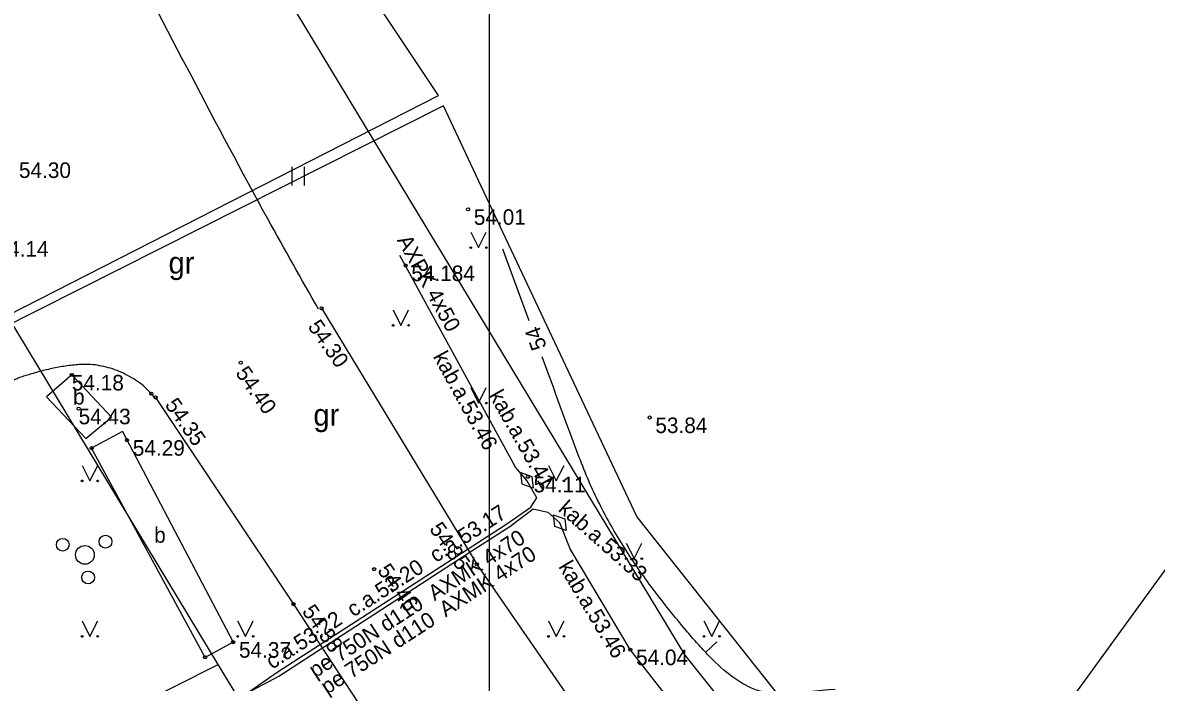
# Model space of a CAD drawing. Extents: x 578395 to 578590, y 418519 to 418816.
# Drawn here: x 578485.34 to 578521.8, y 418556.02 to 418577.23 of the extents above; entities that cross this region are included whole.
import ezdxf

# ---------------------------------------------------------------- set-up
doc = ezdxf.new("R2010")
doc.units = 0
for name, color, linetype in [('BUVE_BDET_####_####_#', 7, 'Continuous'), ('BUVE_BDET_####_TKST_#', 7, 'Continuous'), ('CELI_CMAL_####_####_#', 7, 'Continuous'), ('CELI_CSEG_####_TKST_#', 7, 'Continuous'), ('ELEK_ACRL_####_####_#', 7, 'Continuous'), ('ELEK_ACRL_####_TKST_#', 7, 'Continuous'), ('ELEK_ELEM_####_####_#', 7, 'Continuous'), ('ELEK_VADP_ZSPR_####_#', 7, 'Continuous'), ('ELEK_VADP_ZSPR_####_I', 7, 'Continuous'), ('ELEK_VADP_ZSPR_TKST_#', 7, 'Continuous'), ('ELEK_VADP_ZSPR_TKST_I', 7, 'Continuous'), ('RAMI_PLAN_####_TKST_#', 7, 'Continuous'), ('RELJ_AATZ_####_TKST_#', 7, 'Continuous'), ('RELJ_ELEM_####_####_#', 7, 'Continuous'), ('RELJ_HORZ_####_TKST_#', 7, 'Continuous'), ('RELJ_HORZ_RESN_####_#', 7, 'Continuous'), ('ROBZ_UZMR_####_####_#', 7, 'Continuous'), ('TERT_ELEM_####_####_#', 7, 'Continuous')]:
    doc.layers.add(name, color=color, linetype=linetype)

msp = doc.modelspace()

# ---------------------------------------------------------------- linework, layer by layer
at = {"layer": 'BUVE_BDET_####_####_#'}
for p, q in [((578488.545, 418564.091), (578487.553, 418563.554)), ((578488.545, 418564.091), (578492.108, 418557.315)), ((578491.201, 418556.824), (578487.553, 418563.554)), ((578492.108, 418557.315), (578491.201, 418556.824))]:
    msp.add_line(p, q, dxfattribs=at)
msp.add_lwpolyline([(578486.917, 418565.908), (578486.097, 418565.2), (578487.369, 418563.868), (578488.193, 418564.552), (578486.917, 418565.908)], dxfattribs=at)
at = {"layer": 'CELI_CMAL_####_####_#'}
for points in [[(578494.951, 418568.05), (578499.945, 418559.817), (578500, 418559.737)], [(578489.611, 418565.18), (578494.048, 418558.537), (578500, 418549.461)], [(578500, 418559.737), (578506.766, 418549.939)]]:
    msp.add_lwpolyline(points, dxfattribs=at)
for points in [[(578494.854, 418568.017), (578493.222, 418570.924), (578490.763, 418575.52), (578488.331, 418580.13), (578485.806, 418584.688), (578479.899, 418594.609), (578471.211, 418607.779)], [(578489.589, 418565.162), (578489.474, 418565.302), (578489.267, 418565.515), (578489.033, 418565.697), (578488.777, 418565.854), (578488.508, 418565.991), (578488.231, 418566.099), (578487.946, 418566.175), (578487.378, 418566.248), (578487.157, 418566.239), (578486.936, 418566.22), (578486.495, 418566.155), (578486.273, 418566.111), (578486.052, 418566.06), (578485.834, 418566.002), (578485.615, 418565.94), (578485.445, 418565.89), (578485.276, 418565.835), (578485.114, 418565.767), (578484.962, 418565.679), (578480.688, 418562.724)]]:
    msp.add_spline(points, degree=3, dxfattribs=at)
at = {"layer": 'ELEK_ACRL_####_####_#'}
for points in [[(578500, 418560.526), (578500.878, 418561.093)], [(578500, 418560.387), (578501.002, 418561.037)], [(578493.524, 418556.347), (578500, 418560.526)], [(578493.577, 418556.224), (578500, 418560.387)]]:
    msp.add_lwpolyline(points, dxfattribs=at)
at = {"layer": 'ELEK_ELEM_####_####_#'}
for points in [[(578501.356, 418562.767), (578501.712, 418562.642), (578501.756, 418562.267), (578501.4, 418562.392)], [(578502.814, 418560.906), (578502.458, 418561.031), (578502.414, 418561.406), (578502.77, 418561.281)]]:
    msp.add_lwpolyline(points, close=True, dxfattribs=at)
at = {"layer": 'ELEK_VADP_ZSPR_####_#'}
for points in [[(578479.187, 418564.935), (578498.707, 418574.895), (578493.264, 418583.075), (578485.065, 418590.965)], [(578500, 418572.157), (578498.867, 418574.559), (578479.335, 418564.716)], [(578521.251, 418540.371), (578510.48, 418554.563), (578505.094, 418561.359), (578500, 418572.157)], [(578500, 418565.116), (578497.464, 418569.749)], [(578501.556, 418562.517), (578501.191, 418562.94), (578500, 418565.116)], [(578508.955, 418551.863), (578504.881, 418557.075), (578502.948, 418560.316), (578502.614, 418561.156)]]:
    msp.add_lwpolyline(points, dxfattribs=at)
at = {"layer": 'ELEK_VADP_ZSPR_####_I'}
for points in [[(578500, 418560.526), (578500.878, 418561.093), (578501.678, 418561.653), (578501.876, 418561.951), (578501.556, 418562.517)], [(578500, 418560.387), (578501.002, 418561.037), (578501.752, 418561.597), (578502.228, 418561.499), (578502.614, 418561.156)], [(578492.567, 418555.687), (578493.524, 418556.347), (578500, 418560.526)], [(578492.567, 418555.687), (578493.577, 418556.224), (578500, 418560.387)]]:
    msp.add_lwpolyline(points, dxfattribs=at)
at = {"layer": 'RAMI_PLAN_####_TKST_#'}
msp.add_line((578500.351, 418519.111), (578500.351, 418667.611), dxfattribs=at)
at = {"layer": 'RELJ_ELEM_####_####_#'}
for centre in [(578499.661, 418571.234), (578497.652, 418569.425), (578494.951, 418568.05), (578492.349, 418566.301), (578486.917, 418565.908), (578489.474, 418565.302), (578489.611, 418565.18), (578487.136, 418564.82), (578505.501, 418564.538), (578488.693, 418563.81), (578487.553, 418563.554), (578501.585, 418562.632), (578499.945, 418559.817), (578496.641, 418559.662), (578494.048, 418558.537), (578492.108, 418557.315), (578491.201, 418556.824), (578504.881, 418557.075)]:
    msp.add_circle(centre, 0.05, dxfattribs=at)
at = {"layer": 'RELJ_HORZ_RESN_####_#'}
for p, q in [((578501.625, 418567.648), (578500.777, 418569.955)), ((578507.667, 418557.325), (578507.303, 418556.982))]:
    msp.add_line(p, q, dxfattribs=at)
msp.add_spline([(578511.475, 418555.796), (578509.769, 418555.66), (578509.541, 418555.655), (578509.319, 418555.678), (578508.888, 418555.794), (578508.084, 418556.26), (578507.35, 418556.933), (578507.008, 418557.307), (578506.682, 418557.685), (578506.133, 418558.351), (578505.615, 418559.017), (578504.68, 418560.369), (578503.885, 418561.771), (578503.544, 418562.502), (578503.241, 418563.256), (578502.051, 418566.491)], degree=3, dxfattribs=at)
at = {"layer": 'ROBZ_UZMR_####_####_#'}
for p, q in [((578469.515, 418618.285), (578506.631, 418556.899)), ((578491.621, 418556.597), (578468.202, 418595.33)), ((578513.707, 418548.097), (578533.748, 418575.711)), ((578506.631, 418556.899), (578513.707, 418548.097)), ((578440.85, 418531.07), (578491.621, 418556.597)), ((578496.218, 418549.102), (578491.621, 418556.597))]:
    msp.add_line(p, q, dxfattribs=at)
at = {"layer": 'TERT_ELEM_####_####_#'}
for p, q in [((578494, 418572), (578494, 418572.6)), ((578494.4, 418572), (578494.4, 418572.6)), ((578499.75, 418570.5), (578500, 418570)), ((578500, 418570), (578500.25, 418570.5)), ((578497.25, 418568), (578497.5, 418567.5)), ((578497.5, 418567.5), (578497.75, 418568)), ((578499.75, 418565.5), (578500, 418565)), ((578500, 418565), (578500.25, 418565.5)), ((578487.25, 418563), (578487.5, 418562.5)), ((578487.5, 418562.5), (578487.75, 418563)), ((578502.25, 418563), (578502.5, 418562.5)), ((578502.5, 418562.5), (578502.75, 418563)), ((578504.75, 418560.5), (578505, 418560)), ((578505, 418560), (578505.25, 418560.5)), ((578487.25, 418558), (578487.5, 418557.5)), ((578487.5, 418557.5), (578487.75, 418558)), ((578492.25, 418558), (578492.5, 418557.5)), ((578492.5, 418557.5), (578492.75, 418558)), ((578502.25, 418558), (578502.5, 418557.5)), ((578502.5, 418557.5), (578502.75, 418558)), ((578507.25, 418558), (578507.5, 418557.5)), ((578507.5, 418557.5), (578507.75, 418558))]:
    msp.add_line(p, q, dxfattribs=at)
for centre, radius in [((578499.75, 418570), 0.028), ((578500.25, 418570), 0.0263), ((578497.25, 418567.5), 0.028), ((578497.75, 418567.5), 0.0263), ((578499.75, 418565), 0.028), ((578500.25, 418565), 0.0263), ((578487.25, 418562.5), 0.028), ((578487.75, 418562.5), 0.0263), ((578502.25, 418562.5), 0.028), ((578502.75, 418562.5), 0.0263), ((578486.625, 418560.446), 0.204), ((578488, 418560.547), 0.207), ((578487.339, 418560.122), 0.301), ((578504.75, 418560), 0.028), ((578505.25, 418560), 0.0263), ((578487.442, 418559.394), 0.205), ((578487.25, 418557.5), 0.028), ((578487.75, 418557.5), 0.0263), ((578492.25, 418557.5), 0.028), ((578492.75, 418557.5), 0.0263), ((578502.25, 418557.5), 0.028), ((578502.75, 418557.5), 0.0263), ((578507.25, 418557.5), 0.028), ((578507.75, 418557.5), 0.0263)]:
    msp.add_circle(centre, radius, dxfattribs=at)

# ---------------------------------------------------------------- texts
at = {"layer": 'BUVE_BDET_####_TKST_#'}
for p in [(578486.957, 418564.955), (578489.565, 418560.511)]:
    msp.add_text('b', height=0.5, dxfattribs=at).set_placement(p)
at = {"layer": 'CELI_CSEG_####_TKST_#'}
for p in [(578490.028, 418569.164), (578494.688, 418564.273)]:
    msp.add_text('gr', height=0.7, dxfattribs=at).set_placement(p)
at = {"layer": 'ELEK_ACRL_####_TKST_#'}
for s, rotation, p in [('c.a.53.17', 32.8367, (578498.631, 418559.855)), ('c.a.53.20', 32.8367, (578495.973, 418558.106)), ('pe 750N d110', 32.9519, (578494.749, 418556.148)), ('c.a.53.22', 33.2577, (578493.363, 418556.425)), ('pe 750N d110', 32.9519, (578495.128, 418555.619))]:
    msp.add_text(s, height=0.5, rotation=rotation, dxfattribs=at).set_placement(p)
at = {"layer": 'ELEK_VADP_ZSPR_TKST_#'}
for s, rotation, p in [('AXPK 4x50', 298.6923, (578497.366, 418570.241)), ('kab.a.53.46', 298.6923, (578498.524, 418566.5)), ('kab.a.53.46', 300.8127, (578502.557, 418559.745))]:
    msp.add_text(s, height=0.5, rotation=rotation, dxfattribs=at).set_placement(p)
at = {"layer": 'ELEK_VADP_ZSPR_TKST_I'}
for s, rotation, p in [('kab.a.53.41', 299.4826, (578500.319, 418565.252)), ('kab.a.53.33', 318.3519, (578502.534, 418561.552)), ('AXMK 4x70', 32.9519, (578498.586, 418558.625)), ('AXMK 4x70', 32.8367, (578498.94, 418558.106))]:
    msp.add_text(s, height=0.5, rotation=rotation, dxfattribs=at).set_placement(p)
at = {"layer": 'RELJ_AATZ_####_TKST_#'}
for s, p in [('54.30', (578485.216, 418572.241)), (' 54.01', (578499.661, 418570.734)), ('54.14', (578484.495, 418569.712)), (' 54.184', (578497.652, 418568.925)), ('54.18', (578486.917, 418565.408)), ('54.43', (578487.136, 418564.32)), (' 53.84', (578505.501, 418564.038)), (' 54.29', (578488.693, 418563.31)), (' 54.11', (578501.585, 418562.132)), (' 54.37', (578492.108, 418556.815)), (' 54.04', (578504.881, 418556.575))]:
    msp.add_text(s, height=0.5, dxfattribs=at).set_placement(p)
for s, p in [(' 54.30', (578494.381, 418567.611)), (' 54.40', (578492.057, 418566.117)), (' 54.35', (578489.786, 418565.095)), (' 54.35', (578498.293, 418561.105)), (' 54.46', (578496.621, 418559.769)), (' 54.38', (578494.196, 418558.454))]:
    msp.add_text(s, height=0.5, rotation=305, dxfattribs=at).set_placement(p)
at = {"layer": 'RELJ_HORZ_####_TKST_#'}
msp.add_text('54', height=0.5, rotation=110.1984, dxfattribs=at).set_placement((578502.199, 418566.812))

doc.saveas('drawing.dxf')
